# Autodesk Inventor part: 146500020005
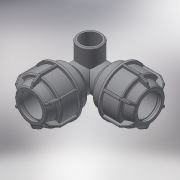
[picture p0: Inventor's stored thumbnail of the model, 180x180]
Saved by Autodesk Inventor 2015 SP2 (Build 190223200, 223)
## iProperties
Created: 2017-08
Part Number: 146500020005
Material: Generic
Description: PLASSON L.14 CORNER TEE ELBOW FEMALE (SILVER) 20-1/2"-20
Document SubType Name: Modeling
Designer: KIM
Density: 1 g/cm^3
Appearance: Default
Author: KIM
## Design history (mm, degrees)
derived "146500.ipt"
feature "Solid1::146500.ipt"
feature "Solid2::146500.ipt"
feature "Solid3::146500.ipt"
tag "TaggingFeature1"
body "Solid1"
body "Solid2"
body "Solid3"
other parameters: "d2" = 39, "d4" = 15 deg, "d5" = 25.74, "d6" = 8.4942, "d10" = 42, "d16" = 20.4, "d17" = 1.95, "d22" = 32, "d24" = 1.95, "d25" = 37.8, "d26" = 31.5, "d27" = 1.95, "d28" = 135 deg, "d29" = 1.17, "d31" = 1, "d46" = 150 deg, "d49" = 2.1, "d50" = 0, "d58" = 0.6, "d61" = 360 deg, "d63" = 17.69945, "d95" = 18.631, "d96" = 24.2203, "d97" = 17, "d98" = 13.97325, "d108" = 1, "d113" = 58, "d114" = 39.78, "d115" = 27.9465, "d116" = 45 deg, "d120" = 90 deg, "d123" = 0, "d124" = 0, "d125" = 4.47144, "d129" = 0, "d131" = 0, "d132" = 0, "d133" = 0, "G_" = 18.631, "E_" = 42, "A_" = 58, "l_" = 39, "l_2" = 17
